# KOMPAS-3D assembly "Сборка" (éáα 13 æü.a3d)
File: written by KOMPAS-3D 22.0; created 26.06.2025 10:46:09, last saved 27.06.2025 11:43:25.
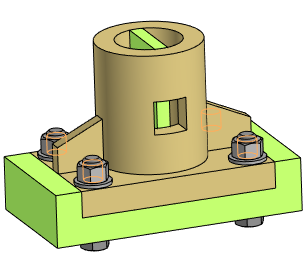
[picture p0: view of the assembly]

Document properties: Автор: Helen; Полное имя файла: C:\Для ноута\Инженерная графика\ППЭ 2025-2026\Варианты 1-38\Вариант 13 СБ\Вар 13 СБ\Вар 13 СБ.a3d

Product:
- Component [detail]: Сборка  | qty 4  | Масса: 0.008612; source file: Шайба 14.m3d
- Component [detail]: Сборка  | qty 4  | Масса: 0.02533; source file: Гайка М14.m3d
- Component [detail]: Болт М14x60 ГОСТ 15591-70  | qty 4  | Масса: 0.091885; source file: ..\..\Вариант 8 СБ\Вар 8 СБ\Болт М14x60 ГОСТ 15591-70.m3d
- Component [detail]: Основание  | designation Вариант 13  | qty 1  | Масса: 3.93188; source file: Основание вар 13.m3d
- Component [detail]: Nodes  | qty 1  | Масса: 4.454505; source file: Корпус вар 13.m3d
- Part/product: Сборка
    Масса: 8.889692

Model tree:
1. Массив по сетке:1  (with: Элемент выдавливания:5, Операция без истории:1, Элемент выдавливания:1)  (4 pattern instances)
     Шаг 1 = 120; Угол раствора = 90; Шаг 2 = 70

Referenced files in D:\MY\WORK\MPEI\ППЭ_2025-2026\Варианты\Вар 1 СБ\: Шайба 14.m3d, Гайка М14.m3d
Referenced files in C:\Для ноута\Инженерная графика\ППЭ 2025-2026\Варианты 1-38\Вариант 13 СБ\Вар 13 СБ\: Основание вар 13.m3d, Корпус вар 13.m3d
Referenced files in C:\Для ноута\Инженерная графика\ППЭ 2025-2026\Варианты 1-38\Вариант 8 СБ\Вар 8 СБ\: Болт М14x60 ГОСТ 15591-70.m3d
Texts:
  Сборка (1)
  Болт М14x60 ГОСТ 15591-70 (1)
  Вариант 13 Основание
